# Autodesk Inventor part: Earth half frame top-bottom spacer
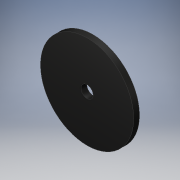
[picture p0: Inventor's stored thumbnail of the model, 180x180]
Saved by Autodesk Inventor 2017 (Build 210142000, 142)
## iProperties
Created: 2016-07
Part Number: Earth half frame top-bottom spacer
Material: Generic
Document SubType Name: Modeling
Designer: Stan
Density: 1 g/cm^3
Appearance: Glossy - Black
Author: Stan
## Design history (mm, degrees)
sketch "Sketch1"
  geometry: C1 r 25.4 at (0, 0); C2 r 3.302 at (0, 0); 1 further point
  constraints: 2 centre point, 2 coincident
  dimensions: "d0" = 50.8 diameter of C1; "d1" = 6.604 diameter of C2
extrude "Extrusion1" new body sketch "Sketch1" distance "d2" = 3.175; taper "d3" = 0 deg
body "Solid1"
